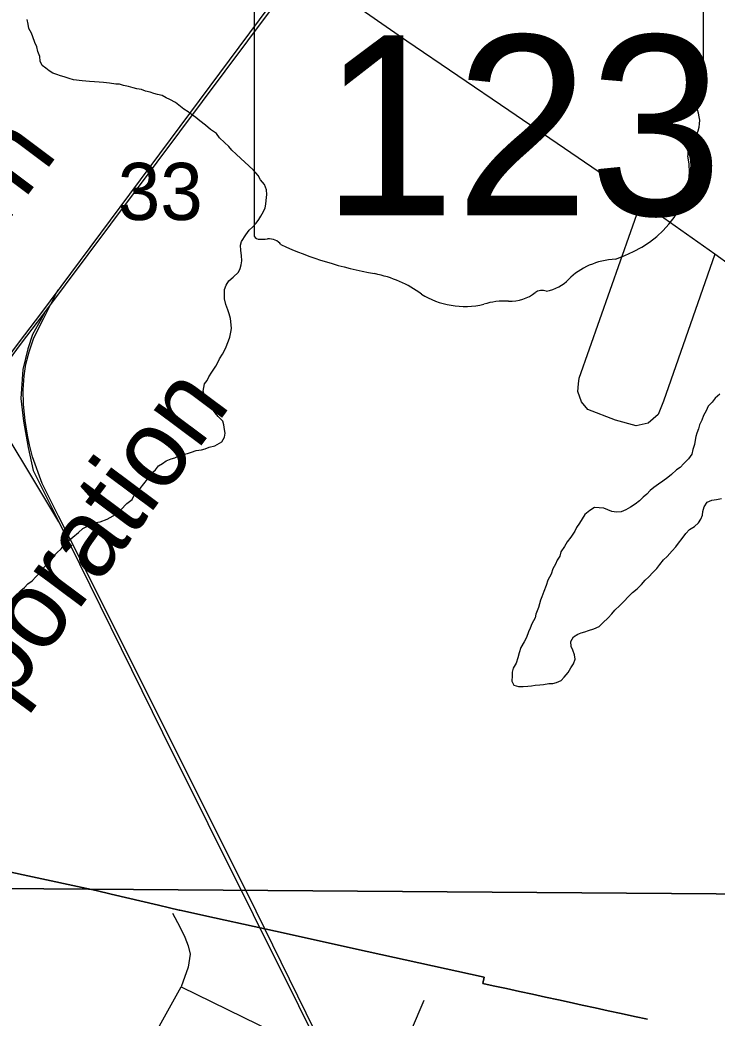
# Model space of a CAD drawing. Extents: x -7.3 to 34, y 0 to 22.
# Drawn here: x 5.185 to 5.696, y 18.585 to 19.316 of the extents above; entities that cross this region are included whole.
import ezdxf

# ---------------------------------------------------------------- set-up
doc = ezdxf.new("R2010")
doc.units = 0
for name, color, linetype in [('GM_X_City_Street', 7, 'Continuous'), ('GM_X_Corporation', 7, 'Continuous'), ('GM_X_Minor_Lake', 7, 'Continuous'), ('GM_X_Minor_River', 7, 'Continuous'), ('GM_X_Rail_Line', 7, 'Continuous'), ('GM_X_Rail_Line_Text', 7, 'Continuous'), ('GM_X_Section_Text', 7, 'Continuous'), ('GM_X_State_Location', 7, 'Continuous'), ('GM_X_State_Route', 7, 'Continuous'), ('GM_X_State_Shield', 7, 'Continuous')]:
    doc.layers.add(name, color=color, linetype=linetype)

msp = doc.modelspace()

# ---------------------------------------------------------------- linework, layer by layer
at = {"layer": 'GM_X_City_Street'}
for points in [[(5.59448, 19.04956), (5.59493, 19.05389), (5.64032, 19.18284)], [(5.69437, 19.14468), (5.6568, 19.03692), (5.65293, 19.02716), (5.64553, 19.02094), (5.63668, 19.01877), (5.62149, 19.02296), (5.60132, 19.03087), (5.59661, 19.03641), (5.59392, 19.04414), (5.59448, 19.04956)], [(5.29684, 18.66185), (5.30211, 18.65189), (5.30596, 18.64427), (5.30831, 18.63788), (5.30981, 18.63167), (5.30831, 18.62227), (5.30305, 18.60789), (5.35973, 18.58019), (5.44546, 18.53538), (5.50346, 18.50564), (5.50698, 18.50378)], [(5.19882, 18.40662), (5.21557, 18.43841), (5.23319, 18.47095), (5.24859, 18.50195), (5.26757, 18.54002), (5.28603, 18.57713), (5.30305, 18.60789)], [(5.44546, 18.53538), (5.46507, 18.56543), (5.47193, 18.5763), (5.48142, 18.59801)]]:
    msp.add_lwpolyline(points, dxfattribs=at)
at = {"layer": 'GM_X_Corporation'}
msp.add_lwpolyline([(4.79036, 19.7043), (5.79575, 19.69545), (5.79417, 18.67513), (4.77473, 18.68274)], close=True, dxfattribs=at)
for points in [[(5.07496, 18.71405), (5.19079, 18.68907), (5.23739, 18.67902), (5.24077, 18.67829), (5.25187, 18.67569), (5.28648, 18.66759), (5.29462, 18.66568), (5.30167, 18.66403), (5.30218, 18.66391), (5.32754, 18.65833), (5.35658, 18.65195), (5.3723, 18.64849), (5.43955, 18.6337), (5.52528, 18.61478), (5.52429, 18.61026), (5.53202, 18.60858), (5.5416, 18.6065), (5.55117, 18.60442), (5.56075, 18.60234), (5.57033, 18.60026), (5.5799, 18.59817), (5.58756, 18.59651), (5.59714, 18.59443), (5.60672, 18.59234), (5.61629, 18.59026), (5.62587, 18.58818), (5.63545, 18.5861), (5.64502, 18.58402)], [(5.64502, 18.58402), (5.63545, 18.5861), (5.62587, 18.58818), (5.61629, 18.59026), (5.60672, 18.59234), (5.59714, 18.59443), (5.58756, 18.59651), (5.5799, 18.59817), (5.57033, 18.60026), (5.56075, 18.60234), (5.55117, 18.60442), (5.5416, 18.6065), (5.53202, 18.60858), (5.52429, 18.61026), (5.52528, 18.61478), (5.43955, 18.6337), (5.3723, 18.64849), (5.35658, 18.65195), (5.32754, 18.65833), (5.30218, 18.66391), (5.30167, 18.66403), (5.29462, 18.66568), (5.28648, 18.66759), (5.25187, 18.67569), (5.24077, 18.67829), (5.24065, 18.67832), (5.23739, 18.67902), (5.19079, 18.68907), (5.07496, 18.71405)], [(4.77473, 18.68274), (5.79417, 18.67513), (5.7934, 18.09073), (5.79302, 18.07181), (5.77506, 18.0074), (5.73946, 17.96949), (5.67616, 17.91091), (5.64186, 17.88092), (5.61187, 17.85918), (5.58272, 17.84083), (5.5487, 17.82522), (5.50746, 17.80863), (5.46897, 17.7969), (5.43319, 17.78816), (5.3971, 17.78244), (5.37466, 17.77797), (5.3538, 17.77612), (5.31176, 17.77658), (5.27247, 17.78116), (5.24116, 17.78747), (5.2216, 17.7943), (5.21005, 17.80363), (5.18434, 17.82497)]]:
    msp.add_lwpolyline(points, dxfattribs=at)
at = {"layer": 'GM_X_Minor_Lake'}
for points in [[(5.69821, 19.04212), (5.69473, 19.03915), (5.69239, 19.03616), (5.68967, 19.03318), (5.68808, 19.0298), (5.68611, 19.02642), (5.6849, 19.02302), (5.68331, 19.01964), (5.68248, 19.01661), (5.68128, 19.0136), (5.68047, 19.01096), (5.68003, 19.0083), (5.67958, 19.00527), (5.67836, 19.0015), (5.67753, 18.9981), (5.67518, 18.99473), (5.67169, 18.99138), (5.66897, 18.9884), (5.66628, 18.98656), (5.66279, 18.98321), (5.66009, 18.98099), (5.65624, 18.97841), (5.65316, 18.9762), (5.64969, 18.97362), (5.64699, 18.97139), (5.64465, 18.96878), (5.64195, 18.96656), (5.63924, 18.96396), (5.63615, 18.96137), (5.63269, 18.95916), (5.62923, 18.95734), (5.62579, 18.95589), (5.62237, 18.95558), (5.61896, 18.95604), (5.61596, 18.95724), (5.61295, 18.95845), (5.60954, 18.9589), (5.60613, 18.95898), (5.60267, 18.95677), (5.59919, 18.95381), (5.59723, 18.95081), (5.59526, 18.94743), (5.59292, 18.94444), (5.59172, 18.94181), (5.58897, 18.9373), (5.58624, 18.93394), (5.58427, 18.93056), (5.58153, 18.92644), (5.58071, 18.92342), (5.57874, 18.92042), (5.57754, 18.91741), (5.57557, 18.91403), (5.57435, 18.91025), (5.57198, 18.90575), (5.57076, 18.90197), (5.56914, 18.89745), (5.56754, 18.89368), (5.56673, 18.89104), (5.56509, 18.88575), (5.56309, 18.88085), (5.56266, 18.8782), (5.56028, 18.87369), (5.55908, 18.87067), (5.55788, 18.86804), (5.55628, 18.86389), (5.55468, 18.86051), (5.55232, 18.85638), (5.5511, 18.8526), (5.54988, 18.84883), (5.54866, 18.84505), (5.54668, 18.8413), (5.54586, 18.83827), (5.5458, 18.83561), (5.54572, 18.83181), (5.54717, 18.82874), (5.55056, 18.82791), (5.55397, 18.82783), (5.5574, 18.82814)], [(5.62467, 18.88711), (5.63399, 18.8968), (5.63746, 18.89938), (5.64057, 18.90273), (5.64329, 18.90572), (5.646, 18.90832), (5.6491, 18.91129), (5.65182, 18.91427), (5.65416, 18.91726), (5.65688, 18.92062), (5.6596, 18.92323), (5.6631, 18.92733), (5.66582, 18.93031), (5.66777, 18.93293), (5.6705, 18.93629), (5.67324, 18.94004), (5.67596, 18.94302), (5.67942, 18.94522), (5.68251, 18.94782), (5.68408, 18.95044), (5.68529, 18.95346), (5.68572, 18.95611), (5.68655, 18.95951), (5.6889, 18.96288), (5.69235, 18.96433), (5.69578, 18.96501), (5.69921, 18.9657)], [(5.5574, 18.82814), (5.56006, 18.82846), (5.56272, 18.82878), (5.56614, 18.82909), (5.5688, 18.82941), (5.57261, 18.83009), (5.57564, 18.83002), (5.57831, 18.83072), (5.58176, 18.83217), (5.58409, 18.83478), (5.58682, 18.83814), (5.58879, 18.84152), (5.59075, 18.84452), (5.59196, 18.84791), (5.59165, 18.85096), (5.59021, 18.85441), (5.58913, 18.8571), (5.58883, 18.86091), (5.5908, 18.86428), (5.59388, 18.86612), (5.59655, 18.8672), (5.59922, 18.8679), (5.6019, 18.86898), (5.60572, 18.87004), (5.60955, 18.87186), (5.61226, 18.87446), (5.61614, 18.87818), (5.61886, 18.88116), (5.62119, 18.88377), (5.62467, 18.88711)]]:
    msp.add_lwpolyline(points, dxfattribs=at)
at = {"layer": 'GM_X_Minor_River'}
for points in [[(5.27066, 19.26578), (5.26802, 19.2666), (5.26463, 19.26743), (5.26085, 19.26828), (5.25784, 19.2691), (5.25518, 19.26916), (5.25065, 19.27002), (5.24611, 19.2705), (5.24308, 19.27056), (5.23967, 19.27102), (5.23588, 19.2711), (5.23058, 19.2716), (5.22415, 19.2725), (5.22113, 19.27332), (5.21737, 19.27455), (5.21473, 19.27536), (5.21209, 19.27618), (5.20908, 19.27739), (5.20646, 19.27896), (5.20385, 19.28092), (5.20124, 19.28288), (5.19979, 19.28595), (5.19948, 19.28938), (5.19805, 19.29321), (5.19736, 19.29665), (5.19591, 19.29972), (5.19449, 19.30393), (5.19341, 19.30661), (5.19159, 19.31007), (5.1909, 19.31313), (5.19021, 19.31656)], [(5.28936, 18.99134), (5.29205, 18.99318), (5.29588, 18.99462), (5.29855, 18.99532), (5.30315, 18.9975), (5.30772, 18.99854), (5.31078, 18.99961), (5.31422, 19.00068), (5.31802, 19.00136), (5.32069, 19.00206), (5.32375, 19.00313), (5.32795, 19.00418), (5.33294, 19.00711), (5.33491, 19.01049), (5.33536, 19.01352), (5.33504, 19.01619), (5.33435, 19.01962), (5.33365, 19.0223), (5.33031, 19.02579), (5.32809, 19.0285), (5.32551, 19.03198), (5.32256, 19.03584), (5.32111, 19.03854), (5.32003, 19.0416), (5.31933, 19.04428), (5.31977, 19.04693), (5.32021, 19.04958), (5.32216, 19.0522), (5.32336, 19.05484), (5.3257, 19.0582), (5.32846, 19.0627), (5.33003, 19.06533), (5.33123, 19.06796), (5.33358, 19.07134), (5.33556, 19.07547), (5.33796, 19.08112), (5.33878, 19.08377), (5.33962, 19.08755), (5.34005, 19.0902), (5.33973, 19.09287), (5.33945, 19.09743), (5.33839, 19.10088), (5.33732, 19.10394), (5.33588, 19.10777), (5.33484, 19.11198), (5.33491, 19.1154), (5.33499, 19.11881), (5.33619, 19.12183), (5.33816, 19.12521), (5.34125, 19.1278), (5.34512, 19.13152), (5.34632, 19.13415), (5.34713, 19.13679), (5.34758, 19.13983), (5.34728, 19.14363), (5.34698, 19.14744), (5.34669, 19.15125), (5.34751, 19.15389), (5.35065, 19.15876), (5.35299, 19.16213), (5.35571, 19.16473), (5.35804, 19.16734), (5.35999, 19.16996), (5.36157, 19.17259), (5.36354, 19.17597), (5.36473, 19.1786), (5.36517, 19.18125), (5.3656, 19.1839), (5.36608, 19.18845), (5.36578, 19.19188), (5.36434, 19.19571), (5.36139, 19.1992), (5.35956, 19.20227), (5.35623, 19.20615), (5.35288, 19.20926), (5.3499, 19.21199), (5.34693, 19.21471), (5.34358, 19.21783), (5.34024, 19.22094), (5.33802, 19.22365), (5.33504, 19.22637), (5.33133, 19.22987), (5.32912, 19.23296), (5.32463, 19.2361), (5.32091, 19.23922), (5.3168, 19.24235), (5.31382, 19.2447), (5.31084, 19.24705), (5.30822, 19.249), (5.30523, 19.25097), (5.3015, 19.25371), (5.29889, 19.25566), (5.29477, 19.25804), (5.29214, 19.25923), (5.28914, 19.26082), (5.28574, 19.26165), (5.28311, 19.26247), (5.28047, 19.26329), (5.27707, 19.26412), (5.27406, 19.26533), (5.27066, 19.26578)], [(5.18296, 18.8952), (5.18568, 18.89819), (5.18839, 18.90041), (5.19072, 18.90302), (5.1938, 18.90523), (5.19652, 18.90822), (5.20001, 18.91194), (5.20197, 18.91456), (5.20469, 18.91754), (5.20819, 18.92165), (5.21207, 18.92574), (5.21517, 18.92872), (5.2179, 18.93208), (5.221, 18.93505), (5.2237, 18.93727), (5.22795, 18.9406), (5.23105, 18.94357), (5.2345, 18.9454), (5.23718, 18.94648), (5.24024, 18.94794), (5.24367, 18.94862), (5.24902, 18.95041), (5.25325, 18.95297), (5.2567, 18.9548), (5.25904, 18.95741), (5.2633, 18.96188), (5.26716, 18.96483), (5.26915, 18.96897), (5.27303, 18.97307), (5.27576, 18.97643), (5.27849, 18.97979), (5.28046, 18.98317), (5.28432, 18.98651), (5.28666, 18.9895), (5.28936, 18.99134)]]:
    msp.add_lwpolyline(points, dxfattribs=at)
at = {"layer": 'GM_X_Rail_Line'}
for points in [[(3.63447, 17.01508), (3.985, 17.48017), (4.37322, 17.99883), (4.5251, 18.20208), (4.79808, 18.56672), (5.07737, 18.93708), (5.15647, 19.04282), (5.18465, 19.08049), (5.20018, 19.101), (5.5499, 19.57109), (5.78633, 19.8846), (5.87764, 20.01389)], [(3.636, 17.01393), (3.98654, 17.47903), (4.37567, 17.99802), (4.52638, 18.19978), (4.79604, 18.55975), (5.07891, 18.93594), (5.15801, 19.04167), (5.18618, 19.07934), (5.20171, 19.09985), (5.55292, 19.56989), (5.78789, 19.88349), (5.87921, 20.01279)], [(5.21358, 18.94857), (5.15624, 19.04335), (5.07115, 19.15581), (5.05358, 19.17523), (5.00144, 19.23013), (4.92948, 19.30254), (4.90267, 19.33078), (4.82446, 19.4204)], [(5.21311, 18.95265), (5.20124, 18.9767), (5.19415, 18.99612), (5.19184, 19.00491), (5.19045, 19.012), (5.18876, 19.02279), (5.18753, 19.0345), (5.18722, 19.04529), (5.18799, 19.05562), (5.18922, 19.0641), (5.19169, 19.07304), (5.19508, 19.08336), (5.20232, 19.09723), (5.21293, 19.11868)], [(5.20286, 19.10138), (5.19427, 19.08586), (5.19082, 19.07531), (5.18708, 19.06003), (5.18571, 19.03901), (5.18765, 19.02228), (5.19088, 19.00307), (5.19454, 18.98612), (5.20296, 18.96945), (5.20937, 18.95681), (5.21358, 18.94857), (5.2894, 18.79415), (5.58862, 18.19408)], [(5.86732, 17.82351), (5.79397, 17.86837), (5.7754, 17.88538), (5.74388, 17.92434), (5.6927, 17.99084), (5.55329, 18.26564), (5.35194, 18.67577), (5.22205, 18.93539), (5.21311, 18.95265)]]:
    msp.add_lwpolyline(points, dxfattribs=at)
at = {"layer": 'GM_X_State_Route'}
msp.add_lwpolyline([(5.84175, 19.04213), (5.78873, 19.07911), (5.73106, 19.11896), (5.70585, 19.13644), (5.69437, 19.14468), (5.64032, 19.18284), (5.61426, 19.2015), (5.54349, 19.25), (5.46868, 19.30078), (5.43827, 19.32175), (5.43428, 19.3247)], dxfattribs=at)
at = {"layer": 'GM_X_State_Shield'}
for p, q in [((5.68622, 19.26286), (5.68622, 19.36754)), ((5.35664, 19.35914), (5.35664, 19.15902)), ((5.68619, 19.26288), (5.68622, 19.26286))]:
    msp.add_line(p, q, dxfattribs=at)
for centre, major_axis, start_param, end_param in [((5.68231, 19.26245), (0.00393, 0), 5.05454, 6.418171), ((5.68537, 19.25517), (0.00568, 0), 1.883978, 3.671073), ((5.64925, 19.24194), (0.03409, 0), 5.934695, 6.695948), ((5.69937, 19.21905), (0.0248, 0), 2.387724, 3.262537), ((5.5884, 19.20573), (0.08742, 0), 5.101752, 6.440018), ((5.36045, 19.15858), (0.00385, 0), 3.00124, 4.508301), ((5.36103, 19.17905), (0.0294, 0), 4.665946, 4.897461), ((5.36705, 19.14747), (0.0106, 0), 0.519207, 1.627899), ((5.50087, 19.32727), (0.2524, 0), 4.195997, 4.488961), ((5.62526, 19.10284), (0.04788, 0), 1.647645, 2.488434), ((5.42562, 19.06911), (0.07897, 0), 0.823519, 1.323587), ((5.5646, 19.13962), (0.02824, 0), 4.937069, 5.64225), ((5.54365, 19.13149), (0.0267, 0), 4.691044, 5.507374), ((5.5678, 19.11211), (0.00752, 0), 1.147584, 2.315152), ((5.51103, 19.14648), (0.05011, 0), 4.026481, 4.996735), ((5.53999, 19.07729), (0.04118, 0), 1.495662, 1.94098)]:
    msp.add_ellipse(centre, major_axis=major_axis, ratio=0.8, start_param=start_param, end_param=end_param, dxfattribs=at)

# ---------------------------------------------------------------- texts
at = {"layer": 'GM_X_Rail_Line_Text'}
for s, rotation, p in [('Norfolk Southern', 53.15911, (4.87253, 18.76318)), ('Corporation', 53.2781, (5.10349, 18.71691))]:
    msp.add_text(s, height=0.0566288, rotation=rotation, dxfattribs=at).set_placement(p)
at = {"layer": 'GM_X_Section_Text'}
msp.add_text('33', height=0.041856, rotation=0.00001, dxfattribs=at).set_placement((5.2567, 19.16969))
at = {"layer": 'GM_X_State_Location'}
for s, p in [('s', (5.51773, 19.24577)), ('r', (5.51772, 19.24577))]:
    msp.add_text(s, height=0.000189, dxfattribs=at).set_placement(p)
msp.add_text('123', height=0.000189, rotation=0.00001, dxfattribs=at).set_placement((5.45087, 19.232))
at = {"layer": 'GM_X_State_Shield'}
msp.add_text('123', height=0.131836, dxfattribs=at).set_placement((5.40611, 19.17313))

doc.saveas('drawing.dxf')
